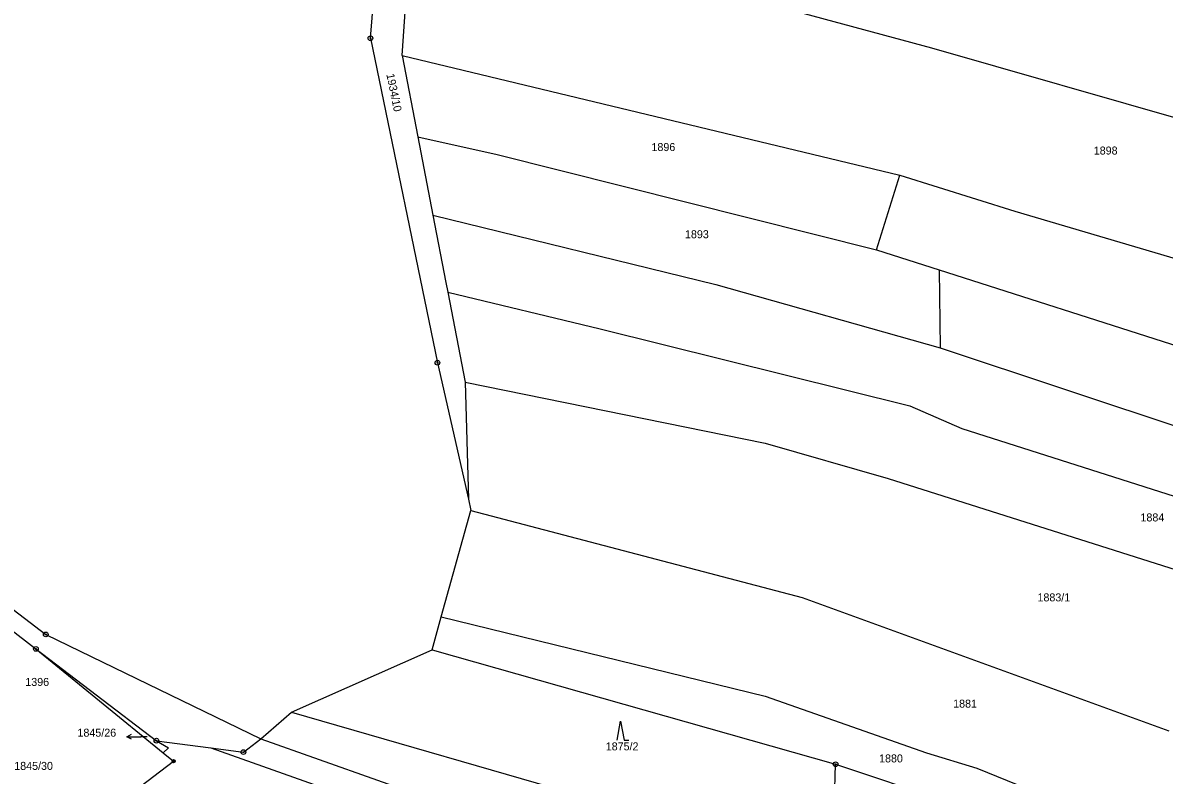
# Model space of a CAD drawing. Extents: x -763205 to -760228, y -1155311 to -1152844.
# Drawn here: x -761608.6 to -761366.2, y -1154935.1 to -1154775.3 of the extents above; entities that cross this region are included whole.
import ezdxf

# ---------------------------------------------------------------- set-up
doc = ezdxf.new("R2010")
doc.units = 0
for name, color, linetype in [('Vrstva 1', 7, 'Continuous'), ('Vrstva 16', 7, 'Continuous'), ('Vrstva 18', 7, 'Continuous'), ('Vrstva 24', 7, 'Continuous'), ('Vrstva 25', 7, 'Continuous'), ('Vrstva 6', 7, 'Continuous')]:
    doc.layers.add(name, color=color, linetype=linetype)

msp = doc.modelspace()

# ---------------------------------------------------------------- linework, layer by layer
at = {"layer": 'Vrstva 1'}
for p, q in [((-761534.79, -1154778.54), (-761530.84, -1154729.16)), ((-761534.79, -1154778.54), (-761520.55, -1154847.48)), ((-761520.55, -1154847.48), (-761513.98, -1154876.49)), ((-761513.98, -1154876.49), (-761513.44, -1154878.89)), ((-761637.88, -1154879.23), (-761603.74, -1154905.21)), ((-761519.75, -1154901.44), (-761513.44, -1154878.89)), ((-761638.12, -1154883.35), (-761605.84, -1154908.28)), ((-761521.71, -1154908.45), (-761519.75, -1154901.44)), ((-761603.74, -1154905.21), (-761558.05, -1154927.37)), ((-761605.84, -1154908.28), (-761578.8, -1154930.33)), ((-761605.84, -1154908.28), (-761580.24, -1154927.78)), ((-761551.57, -1154921.74), (-761521.71, -1154908.45)), ((-761521.71, -1154908.45), (-761436, -1154932.78)), ((-761558.05, -1154927.37), (-761551.57, -1154921.74)), ((-761551.57, -1154921.74), (-761454.31, -1154949.76)), ((-761580.24, -1154927.78), (-761568.69, -1154929.31)), ((-761580.24, -1154927.78), (-761577.65, -1154929.31)), ((-761561.78, -1154930.22), (-761558.05, -1154927.37)), ((-761558.05, -1154927.37), (-761494.1, -1154950.01)), ((-761578.8, -1154930.33), (-761577.65, -1154929.31)), ((-761578.8, -1154930.33), (-761576.59, -1154932.13)), ((-761568.69, -1154929.31), (-761561.78, -1154930.22)), ((-761568.69, -1154929.31), (-761555.49, -1154933.97)), ((-761591.69, -1154943.57), (-761576.59, -1154932.13)), ((-761555.49, -1154933.97), (-761494.82, -1154955.41)), ((-761436.68, -1154954.84), (-761436, -1154932.78))]:
    msp.add_line(p, q, dxfattribs=at)
at = {"layer": 'Vrstva 16'}
for p in [(-761586.55, -1154926.931), (-761582.24, -1154926.93)]:
    msp.add_line(p, (-761583.55, -1154926.93), dxfattribs=at)
msp.add_lwpolyline([(-761585.55, -1154927.43), (-761586.55, -1154926.931), (-761585.55, -1154926.43)], dxfattribs=at)
at = {"layer": 'Vrstva 24'}
for centre, radius in [((-761534.79, -1154778.54), 0.5), ((-761534.79, -1154778.54), 0.1), ((-761520.55, -1154847.48), 0.5), ((-761520.55, -1154847.48), 0.1), ((-761603.74, -1154905.21), 0.5), ((-761603.74, -1154905.21), 0.1), ((-761605.84, -1154908.28), 0.5), ((-761605.84, -1154908.28), 0.1), ((-761580.24, -1154927.78), 0.5), ((-761580.24, -1154927.78), 0.1), ((-761561.78, -1154930.22), 0.5), ((-761561.78, -1154930.22), 0.1), ((-761576.59, -1154932.13), 0.335), ((-761576.59, -1154932.13), 0.067), ((-761436, -1154932.78), 0.5), ((-761436, -1154932.78), 0.1)]:
    msp.add_circle(centre, radius, dxfattribs=at)
at = {"layer": 'Vrstva 25'}
msp.add_lwpolyline([(-761482.39, -1154927.64), (-761481.69, -1154923.64), (-761480.89, -1154927.64), (-761479.89, -1154927.64)], dxfattribs=at)
at = {"layer": 'Vrstva 6'}
for p, q in [((-761528.04, -1154782.21), (-761525.97, -1154750.67)), ((-761525.97, -1154750.67), (-761415.65, -1154780.61)), ((-761415.65, -1154780.61), (-761343.54, -1154801.21)), ((-761528.04, -1154782.21), (-761524.72, -1154799.47)), ((-761528.04, -1154782.21), (-761422.36, -1154807.61)), ((-761524.72, -1154799.47), (-761507.85, -1154803.21)), ((-761524.72, -1154799.47), (-761521.51, -1154816.15)), ((-761507.85, -1154803.21), (-761427.31, -1154823.46)), ((-761427.31, -1154823.46), (-761422.36, -1154807.61)), ((-761422.36, -1154807.61), (-761397.94, -1154815.25)), ((-761397.94, -1154815.25), (-761319.37, -1154838.52)), ((-761521.51, -1154816.15), (-761461.43, -1154830.89)), ((-761521.51, -1154816.15), (-761518.75, -1154830.46)), ((-761427.31, -1154823.46), (-761414.02, -1154827.73)), ((-761414.02, -1154827.73), (-761363.09, -1154844.03)), ((-761414.02, -1154827.73), (-761413.81, -1154844.3)), ((-761518.75, -1154830.46), (-761518.36, -1154832.49)), ((-761461.43, -1154830.89), (-761413.81, -1154844.3)), ((-761518.36, -1154832.49), (-761485.98, -1154840.26)), ((-761518.36, -1154832.49), (-761514.68, -1154851.62)), ((-761485.98, -1154840.26), (-761420.24, -1154856.67)), ((-761413.81, -1154844.3), (-761338.23, -1154869.42)), ((-761514.68, -1154851.62), (-761450.99, -1154864.54)), ((-761514.68, -1154851.62), (-761513.98, -1154876.49)), ((-761420.24, -1154856.67), (-761409.17, -1154861.48)), ((-761409.17, -1154861.48), (-761349.34, -1154880.53)), ((-761450.99, -1154864.54), (-761424.84, -1154872.1)), ((-761424.84, -1154872.1), (-761339.52, -1154899.15)), ((-761513.44, -1154878.89), (-761443.1, -1154897.33)), ((-761443.1, -1154897.33), (-761365.22, -1154925.67)), ((-761519.75, -1154901.44), (-761450.98, -1154918.31)), ((-761450.98, -1154918.31), (-761416.72, -1154930.35)), ((-761416.72, -1154930.35), (-761405.99, -1154933.61)), ((-761436, -1154932.78), (-761409.73, -1154941.52)), ((-761405.99, -1154933.61), (-761349.41, -1154956.53))]:
    msp.add_line(p, q, dxfattribs=at)

# ---------------------------------------------------------------- texts
at = {"layer": 'Vrstva 16'}
for s, p in [('1396', (-761608.087, -1154916.15)), ('1845/26', (-761597.01, -1154926.93)), ('1845/30', (-761610.437, -1154933.99))]:
    msp.add_text(s, height=1.7, dxfattribs=at).set_placement(p)
at = {"layer": 'Vrstva 18'}
msp.add_text('1934/10', height=1.7, rotation=281.66605, dxfattribs=at).set_placement((-761531.421, -1154786.215))
for s, height, p in [('1896', 1.7, (-761475.107, -1154802.51)), ('1898', 1.7, (-761381.177, -1154803.25)), ('1893', 1.7, (-761467.987, -1154821.03)), ('1884', 1.7, (-761371.257, -1154881.2)), ('1883/1', 1.7, (-761393.127, -1154898.19)), ('1881', 1.7, (-761411.037, -1154920.76)), ('1845/26', 0.1, (-761582.217, -1154926.93)), ('1875/2', 1.7, (-761484.817, -1154929.84)), ('1880', 1.7, (-761426.767, -1154932.4))]:
    msp.add_text(s, height=height, dxfattribs=at).set_placement(p)

doc.saveas('drawing.dxf')
